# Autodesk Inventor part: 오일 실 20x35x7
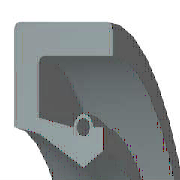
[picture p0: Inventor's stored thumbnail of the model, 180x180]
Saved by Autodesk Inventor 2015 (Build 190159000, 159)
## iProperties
IsCustomPart: 1
Created: 2012-02
Part Number: 오일 실 20x35x7
Material: 고무
Description: 회전 샤프트 립 유형 실 2 - 금속 케이스
Document SubType Name: Modeling
Standard: ISO 6194/1
Designer: mduedu
Standards Organization: ISO
Language: ko-KR
Size Designation: 20x35x7-유형 2
Categories: <MemberInstance><Categories><Category DisplayName="샤프트 부품" InternalName="7f7aeb1f-a693-4053-b835-cee3144e0d98" Mnemonic="SHFT"><Category DisplayName="실링" Intern
Density: 0.93 g/cm^3
Appearance: 고무 - 검은색 - 버전 1.1
Author: mduedu
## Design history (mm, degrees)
node "WorkPlane2"
node "WorkPoint1"
node "WorkPlane3"
body "Solid1"
node "스케치1"
revolve "회전1" stored, may be unused: angle "d37" = 360 deg
fillet "모깎기1" dims "d38" = 0.35 (= 0.05 x b)
sketch "스케치2"
  geometry: L1 (16, -0.35)-(16.8, -0.35); L2 (16, 0)-(16, -0.35); L3 (17.5, 0)-(16, 0); L4 (17.5, -7)-(17.5, 0); L5 (12.22, -7)-(17.5, -7); L6 (11.283, -4.2)-(12.22, -7); L7 (10.601, -3.72)-(11.283, -4.2); L8 (10, -1.925)-(10.601, -3.72); L9 (10.789, -1.05)-(10, -1.925); L10 (12.664, -1.05)-(10.789, -1.05); L11 (12.664, -1.925)-(12.664, -1.05); L12 (12.664, -5.6)-(12.664, -3.325); L13 (13.664, -5.6)-(12.664, -5.6); L14 (13.664, -6.3)-(13.664, -5.6); L15 (16.8, -6.3)-(13.664, -6.3); L16 (16.8, -0.35)-(16.8, -6.3); L17 (0, -15.959)-(0, 2.029); L18 (0, -15.959)-(0, 2.029); L19 (0, -19.557)-(0, 5.626) reference; L20 (-5.2, 0)-(31.2, 0) reference; A1 r 0.7 centre (12.664, -2.625) between (12.664, -3.325) and (12.664, -1.925)
  constraints: 36 end point, 7 vertical, 6 horizontal, 2 collinear, 2 point on circle, 1 centre point, 1 parallel, 1 point on line
  dimensions: "d2" = 0.35 distance of L2.start L1.start (= 0.05 x b); "d4" = 7 distance of L4.start L3.start (= b); "d6" = 0.7 horizontal distance of L1.end L3.start (= 0.1 x b); "d8" = 0.7 horizontal distance of L15.start L4.start (= 0.1 x b); "d10" = 0.7 distance of L14.start L13.start (= 0.1 x b); "d12" = 0.7 vertical distance of L1.end L10.start (= 0.1 x b); "d14" = 0.875 distance of L11.start L10.start (= 0.125 x b); "d16" = 0.7 radius of A1 (= 0.1 x b); "d18" = 0 horizontal distance of A1.centre L12.end; "d20" = 0.875 vertical distance of L9.start L8.start (= 0.125 x b); "d22" = 1.79487 vertical distance of L8.start L7.start (= 0.25641 x b); "d24" = 2.8 vertical distance of L6.start L5.start (= 0.4 x b); "d26" = 1.5 distance of L3.start L2.start (= 0.1 x dd - 0.1 x Diam); "d28" = 0.78947 horizontal distance of L9.start L8.start (= 0.0526316 x dd - 0.0526316 x Diam); "d30" = 1.875 distance of L10.start L9.start (= 0.125 x dd - 0.125 x Diam); "d32" = 1 distance of L13.start L12.start (= 0.0666667 x dd - 0.0666667 x Diam); "d34" = 0.9375 horizontal distance of L6.start L5.start (= 0.0625 x dd - 0.0625 x Diam); "d36" = 0.68182 horizontal distance of L7.start L6.start (= 0.0454545 x dd - 0.0454545 x Diam); "msp_d39" = 20 diameter of L8.start L17 (= Diam); "msp_d40" = 35 diameter of L4 L17 (= dd)
other parameters: "dd" = 35 [user parameter; used in 7 equation terms], "Diam" = 20 [user parameter; used in 7 equation terms], "b" = 7 [user parameter; used in 13 equation terms], "d0" = -7 (computed from b), "d1" = 0.4 (derived), "d3" = 8 (derived), "d5" = 0.8 (derived), "d7" = 0.8 (derived), "d9" = 0.8 (derived), "d11" = 0.8 (derived), "d13" = 1 (derived), "d15" = 0.8 (derived), "d17" = 0 (derived), "d19" = 1 (derived), "d21" = 2.05128 (derived), "d23" = 3.2 (derived), "d25" = 2 (derived), "d27" = 1.05263 (derived), "d29" = 2.5 (derived), "d31" = 1.33333 (derived), "d33" = 1.25 (derived), "d35" = 0.90909 (derived), "d42" = 0
